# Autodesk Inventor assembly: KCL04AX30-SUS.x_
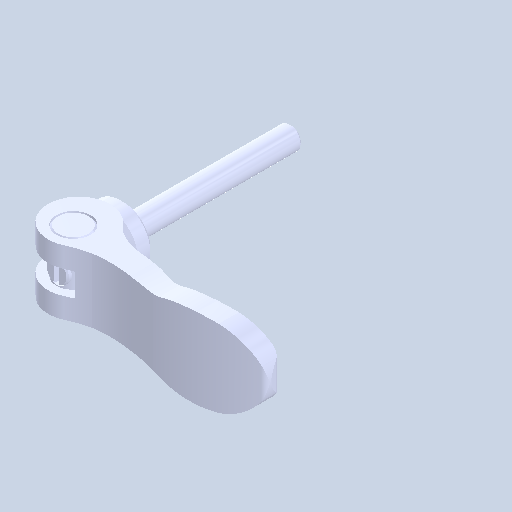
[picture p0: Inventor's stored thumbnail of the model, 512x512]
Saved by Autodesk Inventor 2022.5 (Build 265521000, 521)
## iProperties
Created: 2024-08
Part Number: KCL04AX30-SUS.x_
Document SubType Name: Assembly
Designer: ImaoCorp
Author: ImaoCorp
Sending System: SOLIDWORKS 2022-2022290
MC: AMD64
MC_MODEL: Intel64 Family 6 Model 60 Stepping 3, GenuineIntel
OS: Windows_NT
FRU: Parasolid Version 33.1, build 260,  4-25-2022
FORMAT: text
GUISE: transmit
KEY: FILEKCL04AX30-SUS.x_t
DATE: Thu Aug 29 10:47:40 2024
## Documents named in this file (5)
- Y:\5.更新分\2024年対応\1001_KCL\データ\kcl04ax30-sus\KCL04AX30-SUS.x_.iam
- Y:\5.更新分\2024年対応\1001_KCL\データ\kcl04ax30-sus\KCL04AX30-SUS_01.ipt
- Y:\5.更新分\2024年対応\1001_KCL\データ\kcl04ax30-sus\KCL04AX30-SUS_02.ipt
- Y:\5.更新分\2024年対応\1001_KCL\データ\kcl04ax30-sus\KCL04AX30-SUS_03.ipt
- Y:\5.更新分\2024年対応\1001_KCL\データ\kcl04ax30-sus\KCL04AX30-SUS_04.ipt
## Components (4 placed, 4 different names)
1. KCL04AX30-SUS_01
2. KCL04AX30-SUS_02
3. KCL04AX30-SUS_03
4. KCL04AX30-SUS_04
